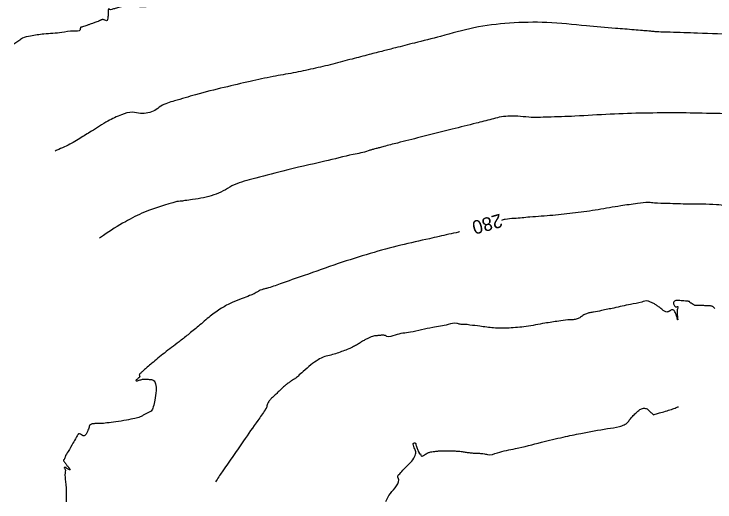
# Model space of a CAD drawing. Extents: x -478102 to -473059, y -1117705 to -1114104.
# Drawn here: x -475865.3 to -475658.9, y -1116104.9 to -1115961.3 of the extents above; entities that cross this region are included whole.
import ezdxf

# ---------------------------------------------------------------- set-up
doc = ezdxf.new("R2010")
doc.units = 0
for name, color, linetype in [('Vrstevnice_hlavni', 7, 'Continuous'), ('Vrstevnice_popis', 7, 'Continuous'), ('Vrstevnice_vedlejsi', 7, 'Continuous')]:
    doc.layers.add(name, color=color, linetype=linetype)

msp = doc.modelspace()

# ---------------------------------------------------------------- linework, layer by layer
at = {"layer": 'Vrstevnice_hlavni'}
for points in [[(-475721.656, -1116021.921), (-475720.62, -1116021.633), (-475718.031, -1116021.363), (-475713.372, -1116020.965), (-475706.644, -1116020.44), (-475699.945, -1116019.714), (-475693.277, -1116018.786), (-475686.638, -1116017.656), (-475681.664, -1116016.951), (-475678.354, -1116016.672), (-475676.708, -1116016.818), (-475672.839, -1116016.975), (-475666.748, -1116017.142), (-475658.434, -1116017.321), (-475652.719, -1116017.574), (-475649.603, -1116017.901), (-475649.085, -1116018.302), (-475648.228, -1116018.475), (-475647.031, -1116018.42), (-475645.495, -1116018.137), (-475643.612, -1116018.247), (-475641.384, -1116018.748), (-475638.81, -1116019.641), (-475635.789, -1116020.801), (-475632.319, -1116022.229), (-475628.402, -1116023.923), (-475624.07, -1116026.55), (-475619.323, -1116030.11), (-475614.162, -1116034.601), (-475609.969, -1116038.094), (-475606.743, -1116040.588), (-475604.485, -1116042.082), (-475602.862, -1116043.199), (-475601.875, -1116043.937), (-475601.523, -1116044.296), (-475601.083, -1116044.742), (-475600.556, -1116045.273), (-475599.94, -1116045.889), (-475598.642, -1116047.373), (-475596.662, -1116049.725), (-475594.001, -1116052.945), (-475592.012, -1116055.361), (-475590.694, -1116056.974), (-475590.049, -1116057.784), (-475589.53, -1116058.403), (-475589.136, -1116058.832), (-475588.867, -1116059.071), (-475588.149, -1116059.767), (-475586.98, -1116060.92), (-475585.362, -1116062.531), (-475583.813, -1116064.295), (-475582.333, -1116066.213), (-475580.922, -1116068.285), (-475581.168, -1116072.263)], [(-475734.144, -1116025.39), (-475734.387, -1116025.457), (-475737.287, -1116026.117), (-475742.967, -1116027.402), (-475751.425, -1116029.313), (-475760.397, -1116031.757), (-475769.883, -1116034.735), (-475779.883, -1116038.248), (-475786.895, -1116040.679), (-475790.919, -1116042.028), (-475791.955, -1116042.297), (-475792.697, -1116042.52), (-475793.144, -1116042.699), (-475793.297, -1116042.833), (-475793.588, -1116043.024), (-475794.017, -1116043.273), (-475794.584, -1116043.58), (-475795.952, -1116044.161), (-475798.119, -1116045.015), (-475801.087, -1116046.144), (-475804.225, -1116047.876), (-475807.532, -1116050.21), (-475811.009, -1116053.146), (-475814.071, -1116055.662), (-475816.718, -1116057.758), (-475818.95, -1116059.434), (-475821.025, -1116061.042), (-475822.943, -1116062.582), (-475824.704, -1116064.055), (-475826.102, -1116065.24), (-475827.136, -1116066.137), (-475827.806, -1116066.746), (-475828.232, -1116067.209), (-475828.413, -1116067.526), (-475828.351, -1116067.695), (-475828.313, -1116067.833), (-475828.301, -1116067.938), (-475828.314, -1116068.011), (-475828.374, -1116068.106), (-475828.48, -1116068.222), (-475828.632, -1116068.36), (-475828.838, -1116068.557), (-475829.097, -1116068.811), (-475829.411, -1116069.123), (-475829.283, -1116069.23), (-475828.713, -1116069.131), (-475827.701, -1116068.826), (-475826.629, -1116068.71), (-475825.498, -1116068.782), (-475824.306, -1116069.042), (-475823.632, -1116070.151), (-475823.476, -1116072.107), (-475823.837, -1116074.911), (-475824.33, -1116076.913), (-475824.954, -1116078.115), (-475825.71, -1116078.516), (-475826.49, -1116078.935), (-475827.294, -1116079.372), (-475828.122, -1116079.828), (-475829.743, -1116080.299), (-475832.155, -1116080.784), (-475835.36, -1116081.285), (-475837.985, -1116081.623), (-475840.031, -1116081.798), (-475841.497, -1116081.812), (-475842.513, -1116081.989), (-475843.078, -1116082.332), (-475843.194, -1116082.84), (-475843.394, -1116083.435), (-475843.681, -1116084.119), (-475844.052, -1116084.891), (-475844.462, -1116085.311), (-475844.911, -1116085.379), (-475845.399, -1116085.096), (-475845.763, -1116084.899), (-475846.004, -1116084.788), (-475846.121, -1116084.764), (-475846.236, -1116084.79), (-475846.348, -1116084.866), (-475846.459, -1116084.992), (-475846.998, -1116085.894), (-475847.966, -1116087.573), (-475849.364, -1116090.027), (-475850.298, -1116091.666), (-475850.771, -1116092.488), (-475850.781, -1116092.494), (-475850.786, -1116092.51), (-475850.787, -1116092.538), (-475850.784, -1116092.577), (-475850.701, -1116092.72), (-475850.538, -1116092.969), (-475850.294, -1116093.322), (-475849.947, -1116093.789), (-475849.495, -1116094.37), (-475848.939, -1116095.066), (-475848.819, -1116095.385), (-475849.137, -1116095.329)], [(-475849.137, -1116095.329), (-475849.892, -1116094.896), (-475850.356, -1116094.685), (-475850.529, -1116094.697), (-475850.411, -1116094.93), (-475850.275, -1116096.32), (-475850.122, -1116098.866), (-475849.952, -1116102.567), (-475849.948, -1116104.864)]]:
    msp.add_spline(points, degree=3, dxfattribs=at)
at = {"layer": 'Vrstevnice_vedlejsi'}
for points in [[(-475626.972, -1115942.227), (-475633.652, -1115941.419), (-475640.935, -1115940.645), (-475648.82, -1115939.903), (-475657.307, -1115939.195), (-475664.335, -1115938.596), (-475669.902, -1115938.106), (-475674.01, -1115937.726), (-475677.949, -1115937.374), (-475681.719, -1115937.05), (-475685.32, -1115936.754), (-475691.201, -1115936.797), (-475699.36, -1115937.18), (-475709.798, -1115937.903), (-475718.974, -1115938.831), (-475726.889, -1115939.965), (-475733.543, -1115941.305), (-475740.089, -1115942.662), (-475746.53, -1115944.036), (-475752.864, -1115945.428), (-475757.924, -1115946.136), (-475761.71, -1115946.159), (-475764.223, -1115945.498), (-475766.865, -1115945.187), (-475769.638, -1115945.226), (-475772.542, -1115945.614), (-475776.131, -1115946.405), (-475780.407, -1115947.599), (-475785.368, -1115949.196), (-475789.432, -1115950.28), (-475792.598, -1115950.851), (-475794.867, -1115950.909), (-475797.111, -1115951.066), (-475799.331, -1115951.321), (-475801.527, -1115951.675), (-475805.142, -1115952.648), (-475810.177, -1115954.237), (-475816.63, -1115956.445), (-475821.354, -1115957.989), (-475824.348, -1115958.868), (-475825.613, -1115959.083), (-475827.093, -1115959.169), (-475828.79, -1115959.124), (-475830.704, -1115958.95), (-475832.462, -1115958.989), (-475834.065, -1115959.24), (-475835.512, -1115959.703), (-475836.55, -1115959.941), (-475837.178, -1115959.951), (-475837.396, -1115959.735), (-475837.545, -1115960.028), (-475837.626, -1115960.829), (-475837.639, -1115962.139), (-475837.796, -1115962.954), (-475838.097, -1115963.274), (-475838.543, -1115963.1), (-475838.899, -1115962.986), (-475839.166, -1115962.933), (-475839.344, -1115962.941), (-475839.537, -1115962.987), (-475839.744, -1115963.071), (-475839.966, -1115963.193), (-475840.121, -1115963.279), (-475840.208, -1115963.327), (-475840.228, -1115963.339), (-475840.572, -1115963.463), (-475841.24, -1115963.701), (-475842.231, -1115964.051), (-475842.916, -1115964.294), (-475843.295, -1115964.429), (-475843.367, -1115964.456), (-475843.651, -1115964.554), (-475844.147, -1115964.725), (-475844.855, -1115964.967), (-475845.344, -1115965.127), (-475845.613, -1115965.204), (-475845.664, -1115965.198), (-475845.724, -1115965.315), (-475845.794, -1115965.554), (-475845.874, -1115965.916), (-475847.693, -1115966.311), (-475851.252, -1115966.74), (-475856.551, -1115967.203), (-475860.42, -1115967.77), (-475862.861, -1115968.441), (-475863.873, -1115969.215), (-475865.092, -1115969.981), (-475865.318, -1115970.108)], [(-475696.749, -1115964.79), (-475708.382, -1115963.809), (-475719.414, -1115963.995), (-475729.845, -1115965.347), (-475739.674, -1115967.866), (-475747.393, -1115969.839), (-475753.002, -1115971.265), (-475756.501, -1115972.144), (-475760.74, -1115973.233), (-475765.718, -1115974.53), (-475771.436, -1115976.036), (-475777.225, -1115977.399), (-475783.086, -1115978.619), (-475789.018, -1115979.697), (-475795.787, -1115981.125), (-475803.393, -1115982.904), (-475811.837, -1115985.034), (-475818.066, -1115986.874), (-475822.082, -1115988.423), (-475823.884, -1115989.681), (-475825.876, -1115990.396), (-475828.057, -1115990.567), (-475830.428, -1115990.195), (-475833.631, -1115990.944), (-475837.668, -1115992.815), (-475842.537, -1115995.808), (-475845.938, -1115997.893), (-475847.869, -1115999.071), (-475848.332, -1115999.341), (-475852.684, -1116001.38), (-475853.196, -1116001.617)], [(-475517.572, -1116066.619), (-475517.753, -1116066.428), (-475521.164, -1116062.876), (-475524.777, -1116059.186), (-475527.496, -1116056.526), (-475529.321, -1116054.896), (-475530.252, -1116054.296), (-475531.462, -1116053.606), (-475532.952, -1116052.825), (-475534.721, -1116051.953), (-475536.209, -1116051.042), (-475537.415, -1116050.093), (-475538.339, -1116049.106), (-475539.112, -1116048.345), (-475539.734, -1116047.811), (-475540.205, -1116047.503), (-475540.671, -1116047.258), (-475541.132, -1116047.075), (-475541.589, -1116046.955), (-475543.06, -1116046.13), (-475545.544, -1116044.599), (-475549.042, -1116042.364), (-475551.91, -1116040.528), (-475554.148, -1116039.093), (-475555.755, -1116038.057), (-475557.153, -1116036.738), (-475558.342, -1116035.138), (-475559.321, -1116033.256), (-475562.018, -1116028.66), (-475566.432, -1116021.35), (-475572.564, -1116011.326), (-475579.461, -1116001.664), (-475587.123, -1115992.364), (-475595.552, -1115983.426), (-475602.158, -1115977.054), (-475606.943, -1115973.249), (-475609.906, -1115972.01), (-475614.951, -1115970.845), (-475622.078, -1115969.752), (-475631.287, -1115968.732), (-475641.35, -1115967.924), (-475652.265, -1115967.327), (-475664.034, -1115966.942), (-475672.102, -1115966.665), (-475676.468, -1115966.495), (-475677.132, -1115966.434), (-475678.388, -1115966.326), (-475680.235, -1115966.172), (-475682.675, -1115965.971), (-475688.18, -1115965.51), (-475696.749, -1115964.79)], [(-475635.042, -1115991.631), (-475637.589, -1115991.349), (-475640.452, -1115991.123), (-475643.63, -1115990.953), (-475647.123, -1115990.838), (-475652.644, -1115990.705), (-475660.192, -1115990.553), (-475669.769, -1115990.383), (-475679.613, -1115990.46), (-475689.725, -1115990.784), (-475700.106, -1115991.356), (-475708.103, -1115991.646), (-475713.716, -1115991.655), (-475716.946, -1115991.383), (-475719.838, -1115991.391), (-475722.394, -1115991.679), (-475724.612, -1115992.248), (-475729.232, -1115993.416), (-475736.252, -1115995.184), (-475745.674, -1115997.552), (-475752.388, -1115999.252), (-475756.395, -1116000.282), (-475757.696, -1116000.643), (-475758.674, -1116000.909), (-475759.329, -1116001.079), (-475759.662, -1116001.154), (-475760.046, -1116001.261), (-475760.481, -1116001.4), (-475760.966, -1116001.571), (-475765.411, -1116002.645), (-475773.817, -1116004.623), (-475786.183, -1116007.506), (-475795.284, -1116009.921), (-475801.119, -1116011.87), (-475803.69, -1116013.353), (-475806.479, -1116014.511), (-475809.486, -1116015.345), (-475812.713, -1116015.854), (-475815.017, -1116016.208), (-475816.399, -1116016.406), (-475817.32, -1116016.489)], [(-475817.32, -1116016.489), (-475826.925, -1116019.603), (-475832.531, -1116022.398), (-475838.942, -1116026.432), (-475840.138, -1116027.275)], [(-475658.86, -1116047.938), (-475659.29, -1116047.586), (-475659.587, -1116047.351), (-475659.75, -1116047.232), (-475659.778, -1116047.229), (-475659.985, -1116047.214), (-475660.371, -1116047.188), (-475660.937, -1116047.15), (-475661.516, -1116047.122), (-475662.11, -1116047.105), (-475662.719, -1116047.097), (-475663.129, -1116047.093), (-475663.34, -1116047.092), (-475663.353, -1116047.093), (-475663.496, -1116047.092), (-475663.77, -1116047.087), (-475664.174, -1116047.079), (-475664.455, -1116047.072), (-475664.613, -1116047.064), (-475664.648, -1116047.056), (-475664.861, -1116046.945), (-475665.254, -1116046.73), (-475665.825, -1116046.412), (-475666.185, -1116046.197), (-475666.335, -1116046.086), (-475666.275, -1116046.078), (-475666.267, -1116046.047), (-475666.312, -1116045.993), (-475666.41, -1116045.917), (-475666.492, -1116045.866), (-475666.558, -1116045.84), (-475666.608, -1116045.839), (-475666.687, -1116045.834), (-475666.797, -1116045.825), (-475666.936, -1116045.813), (-475667.504, -1116045.769), (-475668.501, -1116045.694), (-475669.926, -1116045.588), (-475670.801, -1116045.756), (-475671.126, -1116046.198), (-475670.9, -1116046.915), (-475670.627, -1116047.348), (-475670.308, -1116047.498), (-475669.941, -1116047.363), (-475669.757, -1116047.412), (-475669.755, -1116047.643), (-475669.937, -1116048.057), (-475670.024, -1116048.634), (-475670.018, -1116049.374), (-475669.918, -1116050.278), (-475669.853, -1116050.882), (-475669.823, -1116051.187), (-475669.828, -1116051.193), (-475669.832, -1116051.197), (-475669.833, -1116051.201), (-475669.833, -1116051.204), (-475669.834, -1116051.213), (-475669.835, -1116051.228), (-475669.836, -1116051.249), (-475669.841, -1116051.255), (-475669.848, -1116051.244), (-475669.858, -1116051.218), (-475669.953, -1116050.919), (-475670.131, -1116050.346), (-475670.394, -1116049.501), (-475670.659, -1116048.885), (-475670.926, -1116048.498), (-475671.196, -1116048.341), (-475671.458, -1116048.293), (-475671.713, -1116048.354), (-475671.961, -1116048.524), (-475672.143, -1116048.642), (-475672.26, -1116048.71), (-475672.312, -1116048.727), (-475672.456, -1116048.782), (-475672.694, -1116048.876), (-475673.024, -1116049.008), (-475673.559, -1116048.838), (-475674.297, -1116048.367), (-475675.239, -1116047.594), (-475676.097, -1116046.97), (-475676.869, -1116046.495), (-475677.556, -1116046.167), (-475678.086, -1116045.932), (-475678.459, -1116045.788), (-475678.675, -1116045.737), (-475680.444, -1116046.054), (-475683.767, -1116046.741), (-475688.643, -1116047.797), (-475692.258, -1116048.555), (-475694.611, -1116049.015), (-475695.703, -1116049.177), (-475696.747, -1116049.503), (-475697.742, -1116049.991), (-475698.69, -1116050.643), (-475699.748, -1116051.081), (-475700.917, -1116051.306)], [(-475700.917, -1116051.306), (-475702.197, -1116051.318), (-475704.886, -1116051.643), (-475708.985, -1116052.28), (-475714.492, -1116053.23), (-475719.518, -1116053.691), (-475724.06, -1116053.664), (-475728.121, -1116053.148), (-475731.025, -1116052.804), (-475732.775, -1116052.632), (-475733.368, -1116052.632), (-475733.923, -1116052.581), (-475734.439, -1116052.479), (-475734.917, -1116052.326), (-475737.433, -1116052.681), (-475741.989, -1116053.543), (-475748.583, -1116054.912), (-475753.08, -1116055.776), (-475755.48, -1116056.133), (-475755.782, -1116055.985), (-475756.085, -1116055.883), (-475756.389, -1116055.827), (-475756.695, -1116055.817), (-475757.021, -1116055.823), (-475757.369, -1116055.843), (-475757.738, -1116055.879), (-475758.15, -1116055.919), (-475758.606, -1116055.963), (-475759.106, -1116056.011), (-475759.727, -1116056.173), (-475760.47, -1116056.449), (-475761.333, -1116056.838), (-475762.228, -1116057.313), (-475763.155, -1116057.871), (-475764.112, -1116058.515), (-475765.311, -1116059.165), (-475766.751, -1116059.821), (-475768.433, -1116060.485), (-475770.168, -1116061.086), (-475771.957, -1116061.625), (-475773.799, -1116062.103), (-475775.775, -1116063.076), (-475777.886, -1116064.546), (-475780.13, -1116066.512), (-475781.67, -1116067.847), (-475782.506, -1116068.549), (-475782.636, -1116068.62), (-475782.994, -1116068.848), (-475783.58, -1116069.232), (-475784.394, -1116069.774), (-475785.239, -1116070.426), (-475786.116, -1116071.187), (-475787.025, -1116072.058), (-475787.918, -1116072.909), (-475788.796, -1116073.739), (-475789.657, -1116074.549), (-475790.282, -1116075.298), (-475790.672, -1116075.987), (-475790.825, -1116076.616), (-475790.95, -1116077.06), (-475791.046, -1116077.319), (-475791.114, -1116077.392), (-475791.169, -1116077.452), (-475791.211, -1116077.501), (-475791.24, -1116077.537), (-475791.26, -1116077.563), (-475791.268, -1116077.577), (-475791.267, -1116077.581), (-475791.268, -1116077.585), (-475791.272, -1116077.59), (-475791.278, -1116077.596), (-475791.281, -1116077.6), (-475791.283, -1116077.603), (-475791.283, -1116077.604), (-475791.298, -1116077.632), (-475791.329, -1116077.688), (-475791.375, -1116077.772), (-475793.505, -1116080.848), (-475797.72, -1116086.917), (-475804.02, -1116095.979), (-475806.003, -1116098.98)], [(-475690.519, -1116083.271), (-475686.971, -1116082.635), (-475685.583, -1116082.139), (-475684.581, -1116081.465), (-475683.965, -1116080.613), (-475683.161, -1116079.699), (-475682.17, -1116078.723), (-475680.991, -1116077.686), (-475679.887, -1116077.28), (-475678.859, -1116077.506), (-475677.906, -1116078.364), (-475677.245, -1116078.928), (-475676.878, -1116079.199), (-475676.804, -1116079.176), (-475676.122, -1116078.971), (-475674.833, -1116078.584), (-475672.936, -1116078.015), (-475671.308, -1116077.477), (-475669.949, -1116076.971), (-475669.6, -1116076.824)], [(-475755.762, -1116104.759), (-475754.48, -1116102.382), (-475752.153, -1116097.799), (-475752.287, -1116097.468), (-475751.723, -1116096.597), (-475750.461, -1116095.186), (-475748.503, -1116093.235), (-475747.342, -1116091.55), (-475746.981, -1116090.13), (-475747.419, -1116088.975), (-475747.69, -1116088.18), (-475747.795, -1116087.744), (-475747.733, -1116087.667), (-475747.651, -1116087.598), (-475747.55, -1116087.537), (-475747.429, -1116087.484), (-475747.326, -1116087.459), (-475747.241, -1116087.464), (-475747.174, -1116087.497), (-475747.111, -1116087.538), (-475747.051, -1116087.585), (-475746.995, -1116087.641), (-475746.964, -1116087.705), (-475746.958, -1116087.778), (-475746.979, -1116087.861), (-475746.875, -1116088.226), (-475746.646, -1116088.875), (-475746.293, -1116089.806), (-475746.026, -1116090.414), (-475745.847, -1116090.697), (-475745.754, -1116090.658), (-475745.644, -1116090.741), (-475745.516, -1116090.949), (-475745.372, -1116091.281), (-475745.096, -1116091.372), (-475744.689, -1116091.224), (-475744.152, -1116090.835), (-475743.672, -1116090.537), (-475743.251, -1116090.329), (-475742.889, -1116090.212), (-475742.268, -1116090.095), (-475741.39, -1116089.98), (-475740.254, -1116089.866), (-475738.942, -1116089.804), (-475737.453, -1116089.794), (-475735.788, -1116089.837), (-475734.301, -1116089.93), (-475732.991, -1116090.073), (-475731.858, -1116090.265), (-475730.683, -1116090.409), (-475729.467, -1116090.504), (-475728.208, -1116090.55), (-475727.187, -1116090.633), (-475726.402, -1116090.752), (-475725.855, -1116090.908), (-475722.932, -1116090.381), (-475717.634, -1116089.17), (-475709.961, -1116087.276), (-475703.537, -1116085.778), (-475698.364, -1116084.678), (-475690.519, -1116083.271)]]:
    msp.add_spline(points, degree=3, dxfattribs=at)

# ---------------------------------------------------------------- texts
at = {"layer": 'Vrstevnice_popis'}
msp.add_text(' 280 ', height=4, rotation=195.52286, dxfattribs=at).set_placement((-475720.724, -1116019.587))

doc.saveas('drawing.dxf')
